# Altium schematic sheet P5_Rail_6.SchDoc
size 368 x 228 mm
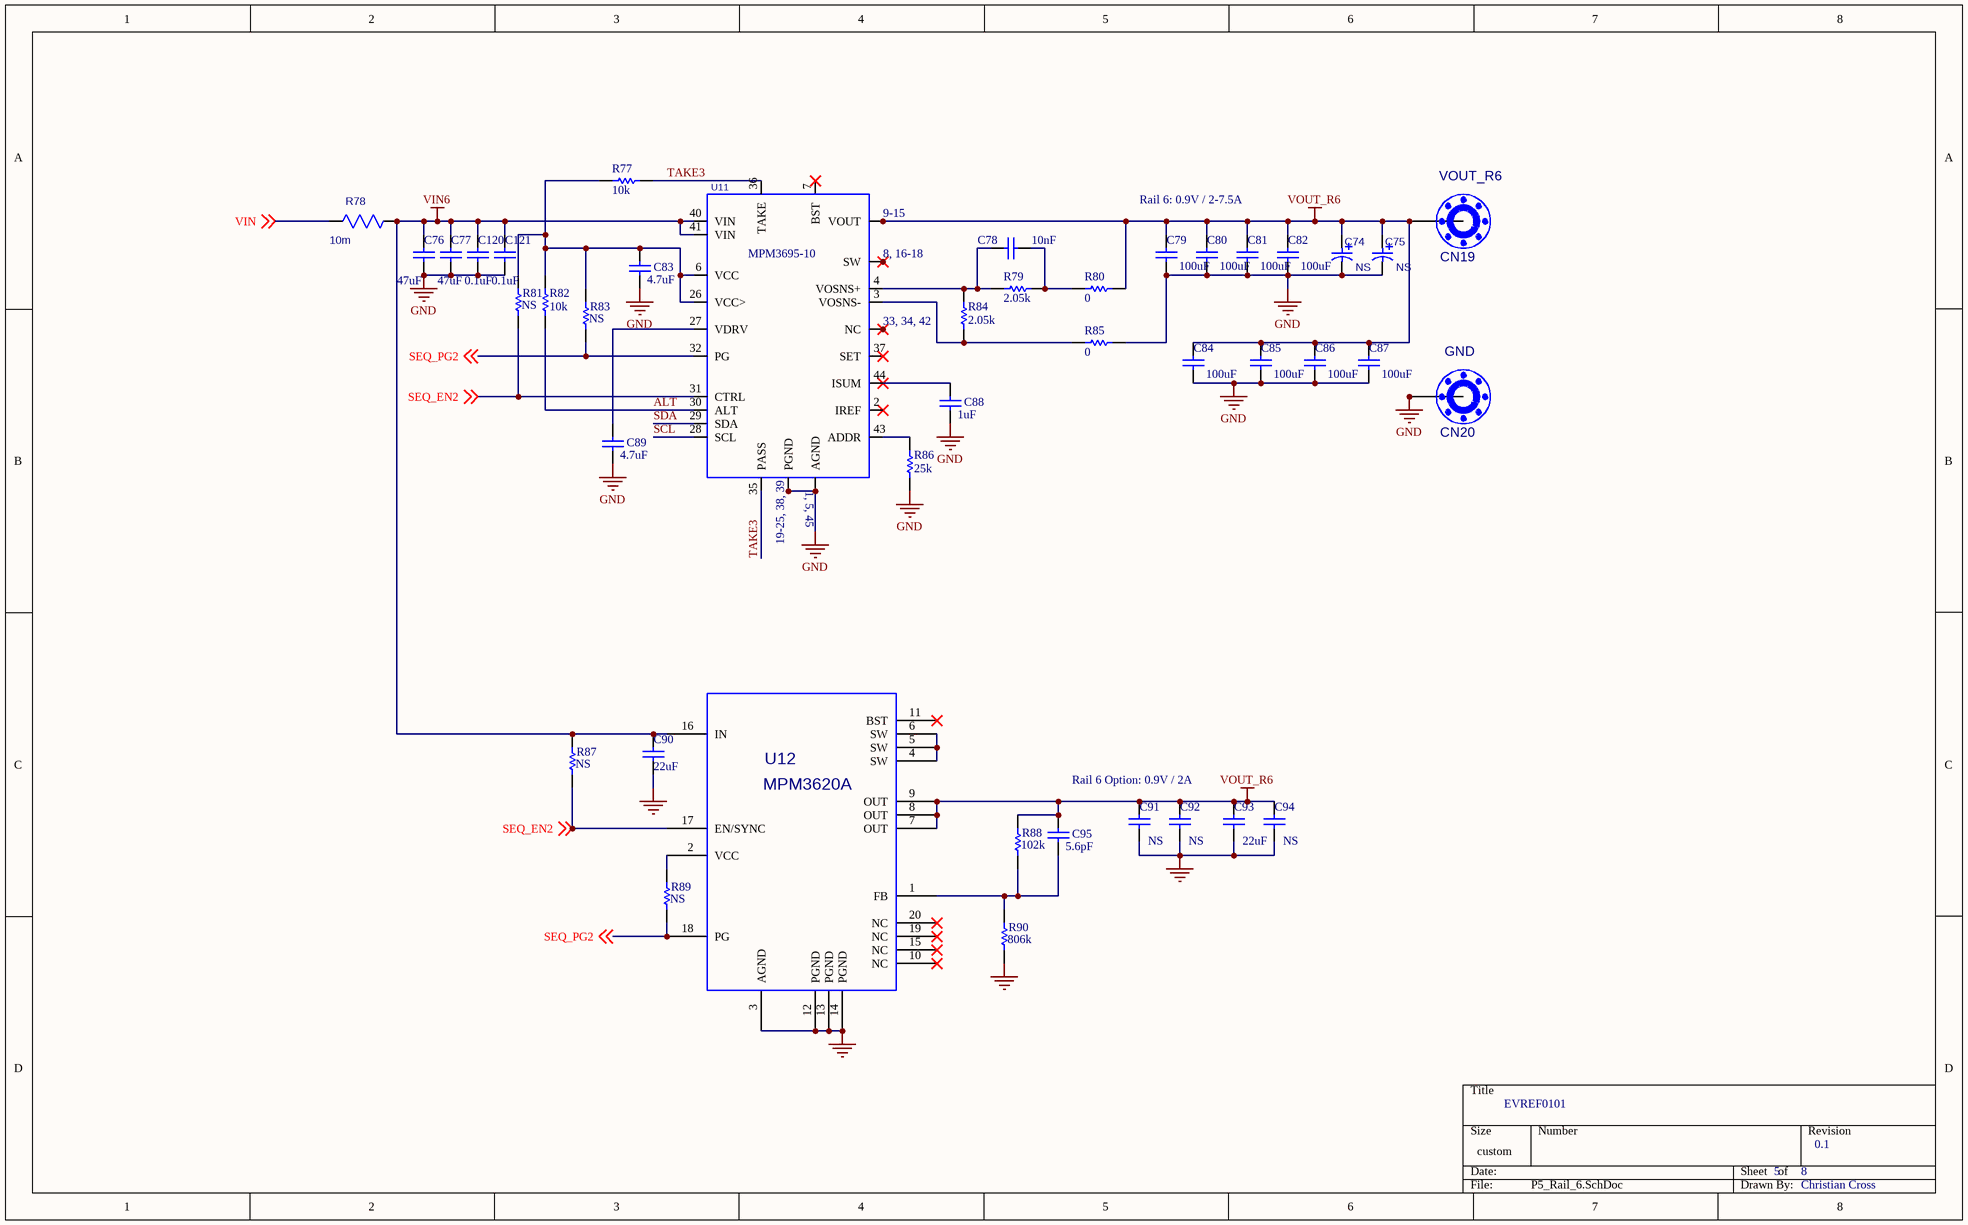
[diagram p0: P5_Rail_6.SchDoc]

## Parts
C74  value NS  [POSCAP/D2]  (hidden comment: POSCAP/D2-D4)
C75  value NS  [POSCAP/D2]  (hidden comment: POSCAP/D2-D4)
C76  47uF  [CAP/1210]
C77  47uF  [CAP/1210]
C78  10nF  [CAP0603]
C79  100uF  [CAP/1210]
C80  100uF  [CAP/1210]
C81  100uF  [CAP/1210]
C82  100uF  [CAP/1210]
C83  4.7uF  [CAP/0603]
C84  100uF  [CAP/1210]
C85  100uF  [CAP/1210]
C86  100uF  [CAP/1210]
C87  100uF  [CAP/1210]
C88  1uF  [CAP/0603]
C89  4.7uF  [CAP/0603]
C90  22uF  [CAP0805]
C91  NS  [CAP0805]
C92  NS  [CAP0805]
C93  22uF  [CAP0805]
C94  NS  [CAP0805]
C95  5.6pF  [CAP/0603]
C120  value 0.1uF  [CAP0402]  (hidden comment: 5.6pF/CAP0603)
C121  value 0.1uF  [CAP0402]  (hidden comment: 5.6pF/CAP0603)
CN19  VOUT_R6  [BANANA-K575]
CN20  GND  [BANANA-K575]
R77  10k  [RES/0603]
R78  value 10m  [RES2512]  (hidden comment: 10m/RES2512)
R79  value 2.05k  [RES0603]  (hidden comment: 4.53/RES0603)
R80  0  [RES/0603]
R81  value NS  [RES/0603]  (hidden comment: 100k/RES0603)
R82  10k  [RES/0603]
R83  value NS  [RES/0603]  (hidden comment: 100k/RES0603)
R84  2.05k  [RES/0603]
R85  0  [RES/0603]
R86  25k  [RES/0603]
R87  value NS  [RES/0603]  (hidden comment: 100k/RES0603)
R88  value 102k  [RES0603]  (hidden comment: 102k/RES0603)
R89  value NS  [RES/0603]  (hidden comment: 100k/RES0603)
R90  value 806k  [RES0603]  (hidden comment: 806k/RES0603)
U11  MPM3695-10  [QFN45-MPM3695-10]  (value not drawn)
U12  Manufacturer P/N: MPM3620A  [QFN20-3X5MM]  (hidden comment: MPM3630A)

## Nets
GND: C74.2 C75.2 C76.1 C77.1 C79.1 C80.1 C81.1 C82.1 C83.1 C84.1 C85.1 C86.1 C87.1 C88.1 C89.1 C90.1 C91.1 C92.1 C93.1 C94.1 C120.1 C121.1 CN20.1 CN20.2 CN20.3 CN20.4 CN20.5 CN20.6 CN20.7 CN20.8 CN20.9 R85.1 R86.1 R90.1 U11.1(AGND) U11.5(AGND) U11.19(PGND) U11.20(PGND) U11.21(PGND) U11.22(PGND) U11.23(PGND) U11.24(PGND) U11.25(PGND) U11.38(PGND) U11.39(PGND) U11.45(AGND) U12.3(AGND) U12.12(PGND) U12.13(PGND) U12.14(PGND)
VIN6: C76.2 C77.2 C90.2 C120.2 C121.2 R78.2 R87.2 U11.40(VIN) U11.41(VIN) U12.16(IN)
VOUT_R6: C74.1 C75.1 C79.2 C80.2 C81.2 C82.2 C84.2 C85.2 C86.2 C87.2 C91.2 C92.2 C93.2 C94.2 C95.2 CN19.1 CN19.2 CN19.3 CN19.4 CN19.5 CN19.6 CN19.7 CN19.8 CN19.9 R80.1 R88.2 U11.9(VOUT) U11.10(VOUT) U11.11(VOUT) U11.12(VOUT) U11.13(VOUT) U11.14(VOUT) U11.15(VOUT) U12.7(OUT) U12.8(OUT) U12.9(OUT)
ALT: R82.1 U11.30(ALT)
SCL: U11.28(SCL)
SDA: U11.29(SDA)
SEQ_EN2: R81.1 R87.1 U11.31(CTRL) U12.17(EN/SYNC) ; off-sheet SEQ_EN2
SEQ_PG2: R83.1 R89.1 U11.32(PG) U12.18(PG) ; off-sheet SEQ_PG2
TAKE3: R77.2 U11.35(PASS) U11.36(TAKE)
VIN: R78.1 ; off-sheet VIN
NetC78_1: C78.1 R79.2 R84.2 U11.4(VOSNS+)
NetC78_2: C78.2 R79.1 R80.2
NetC83_2: C83.2 R77.1 R81.2 R82.2 R83.2 U11.6(VCC) U11.26(VCC>)
NetC88_2: C88.2 U11.44(ISUM)
NetC89_2: C89.2 U11.27(VDRV)
NetC95_1: C95.1 R88.1 R90.2 U12.1(FB)
NetR84_1: R84.1 R85.2 U11.3(VOSNS-)
NetR86_2: R86.2 U11.43(ADDR)
NetR89_2: R89.2 U12.2(VCC)
NetU11_8: U11.8(SW) U11.16(SW) U11.17(SW) U11.18(SW)
NetU11_33: U11.33(NC) U11.34(NC) U11.42(NC)
NetU12_4: U12.4(SW) U12.5(SW) U12.6(SW)

Not connected (* = marked no-connect by the designer): U11 2(IREF)* 7(BST)* 37(SET)*; U12 10(NC)* 11(BST)* 15(NC)* 19(NC)* 20(NC)*

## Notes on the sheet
- Rail 6: 0.9V / 2-7.5A
- Rail 6 Option: 0.9V / 2A
- EVREF0101
- 5
- 8
- 0.1
- Christian Cross

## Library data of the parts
C74 C75 = POSCAP/D2-D4: {Description}; Manufacturer P/N: {Manufacturer P/N}; Manufacturer: {Manufacturer}
C76-C95 C120 C121 = Cap: Capacitor
CN19 CN20 = BANANA-K575: Connector, RCA Jack, R/A; Manufacturer P/N: RCJ-012; Manufacturer: CUI, Inc.
R77 R79 R81-R84 R86-R90 = Res1: Resistor
R78 = RES2512: {Description}; Manufacturer P/N: {Manufacturer P/N}; Manufacturer: {Manufacturer}
R80 R85 = Res1: Resistor; Value: 0ohm
U12 = MPM3630A: 18V/3A DC/DC Module Synchronous Step-Down Regulator; Manufacturer: {Manufacturer}; Value: MPM3620A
